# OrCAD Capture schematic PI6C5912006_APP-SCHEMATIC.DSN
size B; title: PI6C5912006 Application Schematic; rev: 1.0; note: Diodes Inc. Clock IC Application Engineering
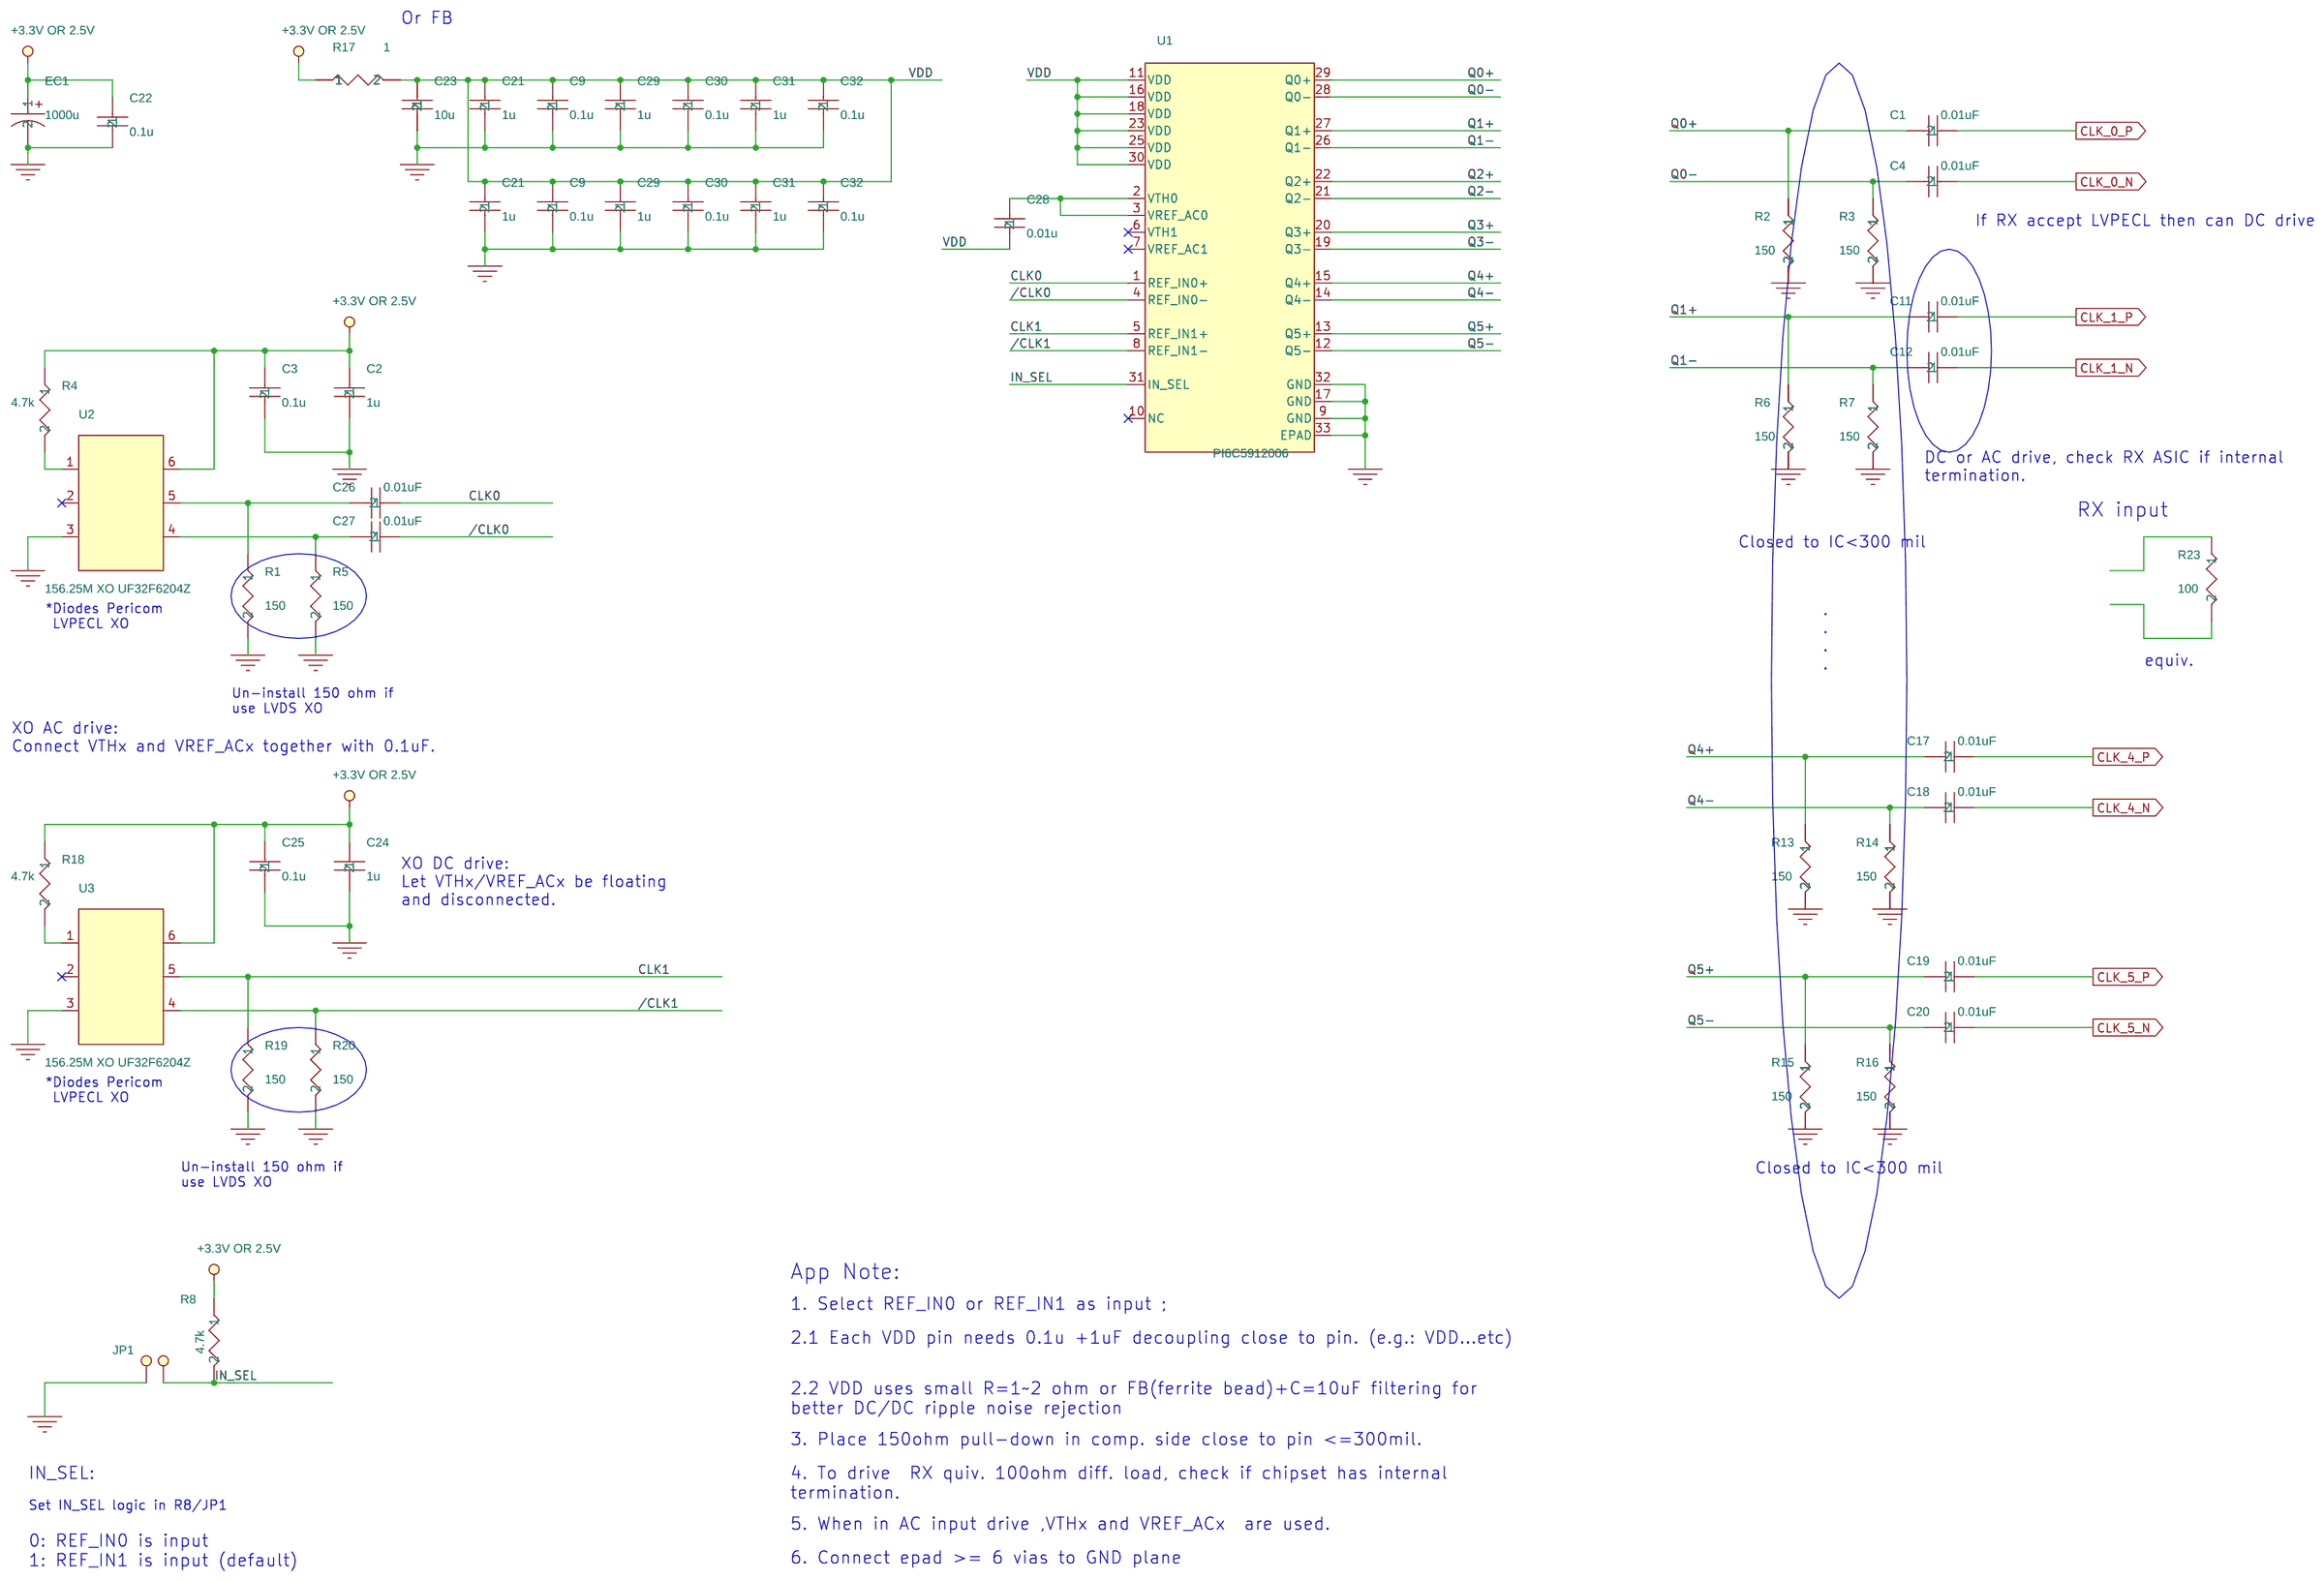
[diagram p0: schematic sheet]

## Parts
C1  0.01uF  [CC_0402]
C2  1u  [CC_0402]
C3  0.1u  [CC_0402]
C4  0.01uF  [CC_0402]
C9  0.1u  [CC_0402]
C9#2  0.1u  [CC_0402]
C11  0.01uF  [CC_0402]
C12  0.01uF  [CC_0402]
C17  0.01uF  [CC_0402]
C18  0.01uF  [CC_0402]
C19  0.01uF  [CC_0402]
C20  0.01uF  [CC_0402]
C21  1u  [CC_0805]
C21#2  1u  [CC_0805]
C22  0.1u  [CC_0402]
C23  10u  [CC_0805]
C24  1u  [CC_0402]
C25  0.1u  [CC_0402]
C26  0.01uF  [CC_0402]
C27  0.01uF  [CC_0402]
C28  0.01u  [CC_0402]
C29  1u  [CC_0805]
C29#2  1u  [CC_0805]
C30  0.1u  [CC_0402]
C30#2  0.1u  [CC_0402]
C31  1u  [CC_0805]
C31#2  1u  [CC_0805]
C32  0.1u  [CC_0402]
C32#2  0.1u  [CC_0402]
EC1  1000u  [CAP1000UF]
JP1  2x1 Pin Header  [2x1 Pin Header]
R1  150  [R_0402]
R2  150  [R_0402]
R3  150  [R_0402]
R4  4.7k  [R_0402]
R5  150  [R_0402]
R6  150  [R_0402]
R7  150  [R_0402]
R8  4.7k  [R_0402]
R13  150  [R_0402]
R14  150  [R_0402]
R15  150  [R_0402]
R16  150  [R_0402]
R17  1  [R_0402]
R18  4.7k  [R_0402]
R19  150  [R_0402]
R20  150  [R_0402]
R23  100  [R_0402]
U1  PI6C5912006
U2  156.25M XO UF32F6204Z  [XO 5X7]
U3  156.25M XO UF32F6204Z  [XO 5X7]

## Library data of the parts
C1 = C_10n_0402
C2 C9#2 C30#2 C32#2 = C_0.1u_0402
C3 = C_0.1u_0402_10
C4 = C_10n_0402_5
C9 = C_0.1u_0402_6
C11 = C_10n_0402_4
C12 = C_10n_0402_2
C17 = C_10n_0402_9
C18 = C_10n_0402_6
C19 = C_10n_0402_8
C20 = C_10n_0402_1
C21 = C_1.0u_0805_4
C21#2 C23 C29#2 C31#2 = C_1.0u_0805
C22 = C_0.1u_0402_1
C24 = C_0.1u_0402_11
C25 = C_0.1u_0402_8
C26 = C_10n_0402_7
C27 = C_10n_0402_3
C28 = C_0.1u_0402_4
C29 = C_1.0u_0805_6
C30 = C_0.1u_0402_9
C31 = C_1.0u_0805_3
C32 = C_0.1u_0402_2
EC1 = C_alum_1000u
JP1 = 2x1_Pin_Header
R1 = R_0402_1
R2 = R_0
R3 = R_0_8
R4 = R_0402_2
R5 = R_0402_4
R6 = R_0_3
R7 = R_0_7
R8 = R_0402_7
R13 = R_0_6
R14 = R_0_5
R15 = R_0_4
R16 = R_0_2
R17 = R_0402
R18 = R_0402_6
R19 = R_0402_3
R20 = R_0402_5
R23 = R_0_1
U1 = PI6C4911504-03_5
U2 U3 = XO_5X7

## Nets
+3.3V or 2.5V: C2.1 C3.1 C22.1 C24.1 C25.1 EC1.1 R4.1 R8.1 R17.1 R18.1 U2.6 U3.6
GND: C2.2 C3.2 C9.2 C9#2.2 C21.2 C21#2.2 C22.2 C23.2 C24.2 C25.2 C29.2 C29#2.2 C30.2 C30#2.2 C31.2 C31#2.2 C32.2 C32#2.2 EC1.2 JP1.1 R1.2 R2.2 R3.2 R5.2 R6.2 R7.2 R13.2 R14.2 R15.2 R16.2 R19.2 R20.2 U1.9(GND) U1.17(GND) U1.32(GND) U1.33(EPAD) U2.3 U3.3
VDD: C9.1 C9#2.1 C21.1 C21#2.1 C23.1 C28.2 C29.1 C29#2.1 C30.1 C30#2.1 C31.1 C31#2.1 C32.1 C32#2.1 R17.2 U1.11(VDD) U1.16(VDD) U1.18(VDD) U1.23(VDD) U1.25(VDD) U1.30(VDD)
/CLK0: C27.1 U1.4(REF_IN0-)
/CLK1: R20.1 U1.8(REF_IN1-) U3.4
CLK0: C26.1 U1.1(REF_IN0+)
CLK1: R19.1 U1.5(REF_IN1+) U3.5
CLK_0_N: C4.1
CLK_0_P: C1.1
CLK_1_N: C12.1
CLK_1_P: C11.1
CLK_4_N: C18.1
CLK_4_P: C17.1
CLK_5_N: C20.1
CLK_5_P: C19.1
IN_SEL: JP1.2 R8.2 U1.31(IN_SEL)
Q0+: C1.2 R2.1 U1.29(Q0+)
Q0-: C4.2 R3.1 U1.28(Q0-)
Q1+: C11.2 R6.1 U1.27(Q1+)
Q1-: C12.2 R7.1 U1.26(Q1-)
Q2+: U1.22(Q2+)
Q2-: U1.21(Q2-)
Q3+: U1.20(Q3+)
Q3-: U1.19(Q3-)
Q4+: C17.2 R13.1 U1.15(Q4+)
Q4-: C18.2 R14.1 U1.14(Q4-)
Q5+: C19.2 R15.1 U1.13(Q5+)
Q5-: C20.2 R16.1 U1.12(Q5-)
N4609914: R18.2 U3.1
N4633501: C27.2 R5.1 U2.4
N4633505: C26.2 R1.1 U2.5
N4633537: R4.2 U2.1
N4636385: C28.1 U1.2(VTH0) U1.3(VREF_AC0)

Not connected (* = marked no-connect by the designer): R23 1 2; U1 6(VTH1)* 7(VREF_AC1)* 10(NC)*; U2 2*; U3 2*

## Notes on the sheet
- Or FB
- If RX accept LVPECL then can DC drive
- DC or AC drive, check RX ASIC if internal
  termination.
- RX input
- Closed to IC<300 mil
- *Diodes Pericom
   LVPECL XO
- .
  .
  .
  .
- equiv.
- Un-install 150 ohm if
  use LVDS XO
- XO AC drive:
  Connect VTHx and VREF_ACx together with 0.1uF.
- XO DC drive:
  Let VTHx/VREF_ACx be floating
  and disconnected.
- *Diodes Pericom
   LVPECL XO
- Un-install 150 ohm if
  use LVDS XO
- Closed to IC<300 mil
- App Note:
- 1. Select REF_IN0 or REF_IN1 as input ;
- 2.1 Each VDD pin needs 0.1u +1uF decoupling close to pin. (e.g.: VDD...etc)
- 2.2 VDD uses small R=1~2 ohm or FB(ferrite bead)+C=10uF filtering for
  better DC/DC ripple noise rejection
- 3. Place 150ohm pull-down in comp. side close to pin <=300mil.
- IN_SEL:
- 4. To drive  RX quiv. 100ohm diff. load, check if chipset has internal
  termination.
- Set IN_SEL logic in R8/JP1
- 5. When in AC input drive ,VTHx and VREF_ACx  are used.
- 0: REF_IN0 is input
  1: REF_IN1 is input (default)
- 6. Connect epad >= 6 vias to GND plane
